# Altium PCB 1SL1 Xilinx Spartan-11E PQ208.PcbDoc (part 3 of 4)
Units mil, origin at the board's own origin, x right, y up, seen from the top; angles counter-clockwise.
Board outline 7086.61 x 1988.19 mil, 2 copper layers (Top Layer, Bottom Layer), stack 29.698 mil thick; 115 components, 126 nets, 642 pads, 225 vias.
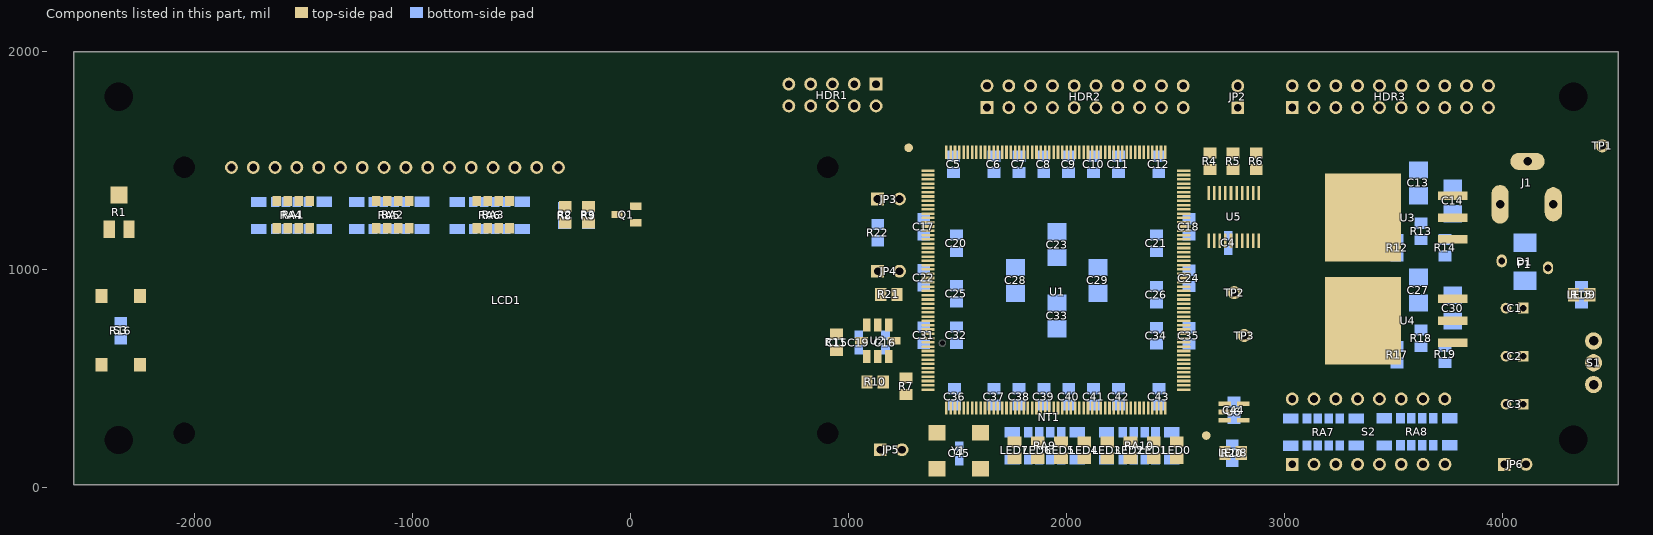
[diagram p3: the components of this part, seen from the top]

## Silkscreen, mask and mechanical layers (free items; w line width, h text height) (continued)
19_FABRICATION_NOTES:
  text "N" at 5217.99,384.2 h46.78
  text "O" at 5243.96,384.2 h46.78
  text "T" at 5269.93,384.2 h46.78
  text "E" at 5288.48,384.2 h46.78
  text "S" at 5307.03,384.2 h46.78
  text "U" at 5333,384.2 h46.78
  text "N" at 5358.97,384.2 h46.78
  text "L" at 5384.93,384.2 h46.78
  text "E" at 5403.48,384.2 h46.78
  text "S" at 5422.03,384.2 h46.78
  text "S" at 5440.58,384.2 h46.78
  text "O" at 5466.55,384.2 h46.78
  text "T" at 5492.52,384.2 h46.78
  text "H" at 5511.07,384.2 h46.78
  text "E" at 5537.04,384.2 h46.78
  text "R" at 5555.58,384.2 h46.78
  text "W" at 5577.84,384.2 h46.78
  text "I" at 5614.94,384.2 h46.78
  text "S" at 5626.07,384.2 h46.78
  text "E" at 5644.62,384.2 h46.78
  text "S" at 5670.59,384.2 h46.78
  text "P" at 5689.14,384.2 h46.78
  text "E" at 5711.4,384.2 h46.78
  text "C" at 5729.94,384.2 h46.78
  text "I" at 5752.2,384.2 h46.78
  text "F" at 5763.33,384.2 h46.78
  text "I" at 5781.88,384.2 h46.78
  text "E" at 5793.01,384.2 h46.78
  text "D" at 5811.56,384.2 h46.78
  text ":" at 5837.53,384.2 h46.78
  text "1" at 5251.37,321.13 h46.78
  text "A" at 5325.54,298.87 h46.78
  text "L" at 5347.8,298.87 h46.78
  text "L" at 5366.35,298.87 h46.78
  text "H" at 5392.32,298.87 h46.78
  text "O" at 5418.29,298.87 h46.78
  text "L" at 5444.26,298.87 h46.78
  text "E" at 5462.81,298.87 h46.78
  text "S" at 5481.35,298.87 h46.78
  text "F" at 5507.32,298.87 h46.78
  text "I" at 5525.87,298.87 h46.78
  text "N" at 5537,298.87 h46.78
  text "I" at 5562.97,298.87 h46.78
  text "S" at 5574.1,298.87 h46.78
  text "H" at 5592.65,298.87 h46.78
  text "E" at 5618.62,298.87 h46.78
  text "D" at 5637.17,298.87 h46.78
  text "S" at 5670.55,298.87 h46.78
  text "I" at 5689.1,298.87 h46.78
  text "Z" at 5700.23,298.87 h46.78
  text "E" at 5718.78,298.87 h46.78
  text "A" at 5744.75,298.87 h46.78
  text "S" at 5767.01,298.87 h46.78
  text "S" at 5792.98,298.87 h46.78
  text "H" at 5811.53,298.87 h46.78
  text "O" at 5837.5,298.87 h46.78
  text "W" at 5863.46,298.87 h46.78
  text "N" at 5900.56,298.87 h46.78
  text "." at 5926.53,298.87 h46.78
  text "M" at 5325.54,235.81 h46.78
  text "A" at 5358.93,235.81 h46.78
  text "T" at 5381.19,235.81 h46.78
  text "E" at 5399.74,235.81 h46.78
  text "R" at 5418.29,235.81 h46.78
  text "I" at 5440.55,235.81 h46.78
  text "A" at 5451.68,235.81 h46.78
  text "L" at 5473.93,235.81 h46.78
  text ":" at 5492.48,235.81 h46.78
  text "0" at 5511.03,235.81 h46.78
  text "." at 5533.29,235.81 h46.78
  text "0" at 5544.42,235.81 h46.78
  text "6" at 5566.68,235.81 h46.78
  text "2" at 5588.94,235.81 h46.78
  text "I" at 5618.62,235.81 h46.78
  text "N" at 5629.75,235.81 h46.78
  text "F" at 5663.13,235.81 h46.78
  text "I" at 5681.68,235.81 h46.78
  text "B" at 5692.81,235.81 h46.78
  text "E" at 5715.07,235.81 h46.78
  text "R" at 5733.62,235.81 h46.78
  text "G" at 5755.88,235.81 h46.78
  text "L" at 5781.85,235.81 h46.78
  text "A" at 5800.4,235.81 h46.78
  text "S" at 5822.66,235.81 h46.78
  text "S" at 5841.21,235.81 h46.78
  text "R" at 5867.17,235.81 h46.78
  text "E" at 5889.43,235.81 h46.78
  text "I" at 5907.98,235.81 h46.78
  text "N" at 5919.11,235.81 h46.78
  text "F" at 5945.08,235.81 h46.78
  text "O" at 5963.63,235.81 h46.78
  text "R" at 5989.6,235.81 h46.78
  text "C" at 6011.86,235.81 h46.78
  text "E" at 6034.11,235.81 h46.78
  text "D" at 6052.66,235.81 h46.78
  text "E" at 6086.05,235.81 h46.78
  text "P" at 6104.6,235.81 h46.78
  text "O" at 6126.86,235.81 h46.78
  text "X" at 6152.83,235.81 h46.78
  text "Y" at 6175.09,235.81 h46.78
  text "," at 6193.64,235.81 h46.78
  text "2" at 5251.37,228.39 h46.78
  text "N" at 5325.54,180.16 h46.78
  text "E" at 5351.51,180.16 h46.78
  text "M" at 5370.06,180.16 h46.78
  text "A" at 5403.45,180.16 h46.78
  text "G" at 5433.13,180.16 h46.78
  text "R" at 5459.1,180.16 h46.78
  text "A" at 5481.35,180.16 h46.78
  text "D" at 5503.61,180.16 h46.78
  text "E" at 5529.58,180.16 h46.78
  text "F" at 5555.55,180.16 h46.78
  text "R" at 5574.1,180.16 h46.78
  text "-" at 5596.36,180.16 h46.78
  text "4" at 5607.49,180.16 h46.78
  text "," at 5629.75,180.16 h46.78
  text "N" at 5648.3,180.16 h46.78
  text "A" at 5674.26,180.16 h46.78
  text "T" at 5696.52,180.16 h46.78
  text "U" at 5715.07,180.16 h46.78
  text "R" at 5741.04,180.16 h46.78
  text "A" at 5763.3,180.16 h46.78
  text "L" at 5785.56,180.16 h46.78
  text "C" at 5811.53,180.16 h46.78
  text "O" at 5833.79,180.16 h46.78
  text "L" at 5859.75,180.16 h46.78
  text "O" at 5878.3,180.16 h46.78
  text "R" at 5904.27,180.16 h46.78
  text "W" at 5933.95,180.16 h46.78
  text "I" at 5971.05,180.16 h46.78
  text "T" at 5982.18,180.16 h46.78
  text "H" at 6000.73,180.16 h46.78
  text "O" at 6026.7,180.16 h46.78
  text "U" at 6052.66,180.16 h46.78
  text "T" at 6078.63,180.16 h46.78
  text "O" at 5325.54,124.51 h46.78
  text "P" at 5351.51,124.51 h46.78
  text "A" at 5373.77,124.51 h46.78
  text "Q" at 5396.03,124.51 h46.78
  text "U" at 5422,124.51 h46.78
  text "E" at 5447.97,124.51 h46.78
  text "R" at 5466.52,124.51 h46.78
  text ";" at 5488.77,124.51 h46.78
  text "1" at 5507.32,124.51 h46.78
  text "O" at 5537,124.51 h46.78
  text "Z" at 5562.97,124.51 h46.78
  text "C" at 5588.94,124.51 h46.78
  text "O" at 5611.2,124.51 h46.78
  text "P" at 5637.17,124.51 h46.78
  text "P" at 5659.43,124.51 h46.78
  text "E" at 5681.68,124.51 h46.78
  text "R" at 5700.23,124.51 h46.78
  text "C" at 5729.91,124.51 h46.78
  text "L" at 5752.17,124.51 h46.78
  text "A" at 5770.72,124.51 h46.78
  text "D" at 5792.98,124.51 h46.78
  text "O" at 5826.37,124.51 h46.78
  text "U" at 5852.33,124.51 h46.78
  text "T" at 5878.3,124.51 h46.78
  text "E" at 5896.85,124.51 h46.78
  text "R" at 5915.4,124.51 h46.78
  text "L" at 5945.08,124.51 h46.78
  text "A" at 5963.63,124.51 h46.78
  text "Y" at 5985.89,124.51 h46.78
  text "E" at 6004.44,124.51 h46.78
  text "R" at 6022.99,124.51 h46.78
  text "S" at 6045.24,124.51 h46.78
  text "." at 6063.79,124.51 h46.78
  text "T" at 6082.34,124.51 h46.78
  text "H" at 6100.89,124.51 h46.78
  text "E" at 6126.86,124.51 h46.78
  text "P" at 5325.54,68.87 h46.78
  text "R" at 5347.8,68.87 h46.78
  text "I" at 5370.06,68.87 h46.78
  text "N" at 5381.19,68.87 h46.78
  text "T" at 5407.16,68.87 h46.78
  text "E" at 5425.71,68.87 h46.78
  text "D" at 5444.26,68.87 h46.78
  text "W" at 5477.64,68.87 h46.78
  text "I" at 5514.74,68.87 h46.78
  text "R" at 5525.87,68.87 h46.78
  text "I" at 5548.13,68.87 h46.78
  text "N" at 5559.26,68.87 h46.78
  text "G" at 5585.23,68.87 h46.78
  text "B" at 5618.62,68.87 h46.78
  text "O" at 5640.88,68.87 h46.78
  text "A" at 5666.84,68.87 h46.78
  text "R" at 5689.1,68.87 h46.78
  text "D" at 5711.36,68.87 h46.78
  text "M" at 5744.75,68.87 h46.78
  text "A" at 5778.14,68.87 h46.78
  text "T" at 5800.4,68.87 h46.78
  text "E" at 5818.95,68.87 h46.78
  text "R" at 5837.5,68.87 h46.78
  text "I" at 5859.75,68.87 h46.78
  text "A" at 5870.88,68.87 h46.78
  text "L" at 5893.14,68.87 h46.78
  text "M" at 5919.11,68.87 h46.78
  text "U" at 5952.5,68.87 h46.78
  text "S" at 5978.47,68.87 h46.78
  text "T" at 5997.02,68.87 h46.78
  text "H" at 6022.99,68.87 h46.78
  text "A" at 6048.95,68.87 h46.78
  text "V" at 6071.21,68.87 h46.78
  text "E" at 6093.47,68.87 h46.78
  text "A" at 6119.44,68.87 h46.78
  text "C" at 5325.54,13.22 h46.78
  text "P" at 5347.8,13.22 h46.78
  text "M" at 5370.06,13.22 h46.78
  text "P" at 5403.45,13.22 h46.78
  text "A" at 5425.71,13.22 h46.78
  text "R" at 5447.97,13.22 h46.78
  text "A" at 5470.23,13.22 h46.78
  text "T" at 5492.48,13.22 h46.78
  text "I" at 5511.03,13.22 h46.78
  text "V" at 5522.16,13.22 h46.78
  text "E" at 5544.42,13.22 h46.78
  text "T" at 5570.39,13.22 h46.78
  text "R" at 5588.94,13.22 h46.78
  text "A" at 5611.2,13.22 h46.78
  text "C" at 5633.46,13.22 h46.78
  text "K" at 5655.72,13.22 h46.78
  text "I" at 5677.97,13.22 h46.78
  text "N" at 5689.1,13.22 h46.78
  text "G" at 5715.07,13.22 h46.78
  text "I" at 5748.46,13.22 h46.78
  text "N" at 5759.59,13.22 h46.78
  text "D" at 5785.56,13.22 h46.78
  text "E" at 5811.53,13.22 h46.78
  text "X" at 5830.08,13.22 h46.78
  text "(" at 5859.75,13.22 h46.78
  text "C" at 5870.88,13.22 h46.78
  text "T" at 5893.14,13.22 h46.78
  text "I" at 5911.69,13.22 h46.78
  text ")" at 5922.82,13.22 h46.78
  text "O" at 5941.37,13.22 h46.78
  text "F" at 5967.34,13.22 h46.78
  text "A" at 5993.31,13.22 h46.78
  text "T" at 6015.57,13.22 h46.78
  text "L" at 6041.53,13.22 h46.78
  text "E" at 6060.08,13.22 h46.78
  text "A" at 6078.63,13.22 h46.78
  text "S" at 6100.89,13.22 h46.78
  text "T" at 6119.44,13.22 h46.78
  text "1" at 6145.41,13.22 h46.78
  text "7" at 6167.67,13.22 h46.78
  text "5" at 6189.93,13.22 h46.78
  text "A" at 5325.54,-42.43 h46.78
  text "N" at 5347.8,-42.43 h46.78
  text "D" at 5373.77,-42.43 h46.78
  text "A" at 5407.16,-42.43 h46.78
  text "U" at 5436.84,-42.43 h46.78
  text "L" at 5462.81,-42.43 h46.78
  text "9" at 5488.77,-42.43 h46.78
  text "4" at 5511.03,-42.43 h46.78
  text "V" at 5533.29,-42.43 h46.78
  text "0" at 5555.55,-42.43 h46.78
  text "F" at 5585.23,-42.43 h46.78
  text "L" at 5603.78,-42.43 h46.78
  text "A" at 5622.33,-42.43 h46.78
  text "M" at 5644.59,-42.43 h46.78
  text "M" at 5677.97,-42.43 h46.78
  text "A" at 5711.36,-42.43 h46.78
  text "B" at 5733.62,-42.43 h46.78
  text "I" at 5755.88,-42.43 h46.78
  text "L" at 5767.01,-42.43 h46.78
  text "I" at 5785.56,-42.43 h46.78
  text "T" at 5796.69,-42.43 h46.78
  text "Y" at 5815.24,-42.43 h46.78
  text "R" at 5841.21,-42.43 h46.78
  text "A" at 5863.46,-42.43 h46.78
  text "T" at 5885.72,-42.43 h46.78
  text "I" at 5904.27,-42.43 h46.78
  text "N" at 5915.4,-42.43 h46.78
  text "G" at 5941.37,-42.43 h46.78
  text "." at 5967.34,-42.43 h46.78
  text "3" at 5251.37,-112.91 h46.78
  text "F" at 5325.54,-135.17 h46.78
  text "I" at 5344.09,-135.17 h46.78
  text "N" at 5355.22,-135.17 h46.78
  text "I" at 5381.19,-135.17 h46.78
  text "S" at 5392.32,-135.17 h46.78
  text "H" at 5410.87,-135.17 h46.78
  text ":" at 5436.84,-135.17 h46.78
  text "E" at 5455.39,-135.17 h46.78
  text "N" at 5473.93,-135.17 h46.78
  text "I" at 5499.9,-135.17 h46.78
  text "G" at 5511.03,-135.17 h46.78
  text "P" at 5544.42,-135.17 h46.78
  text "E" at 5566.68,-135.17 h46.78
  text "R" at 5585.23,-135.17 h46.78
  text "I" at 5614.91,-135.17 h46.78
  text "P" at 5626.04,-135.17 h46.78
  text "C" at 5648.3,-135.17 h46.78
  text "-" at 5670.55,-135.17 h46.78
  text "4" at 5681.68,-135.17 h46.78
  text "5" at 5703.94,-135.17 h46.78
  text "5" at 5726.2,-135.17 h46.78
  text "2" at 5748.46,-135.17 h46.78
  text "." at 5770.72,-135.17 h46.78
  text "A" at 5325.54,-198.24 h46.78
  text "P" at 5347.8,-198.24 h46.78
  text "P" at 5370.06,-198.24 h46.78
  text "L" at 5392.32,-198.24 h46.78
  text "Y" at 5410.87,-198.24 h46.78
  text "G" at 5436.84,-198.24 h46.78
  text "R" at 5462.81,-198.24 h46.78
  text "E" at 5485.06,-198.24 h46.78
  text "E" at 5503.61,-198.24 h46.78
  text "N" at 5522.16,-198.24 h46.78
  text "S" at 5555.55,-198.24 h46.78
  text "O" at 5574.1,-198.24 h46.78
  text "L" at 5600.07,-198.24 h46.78
  text "D" at 5618.62,-198.24 h46.78
  text "E" at 5644.59,-198.24 h46.78
  text "R" at 5663.13,-198.24 h46.78
  text "M" at 5692.81,-198.24 h46.78
  text "A" at 5726.2,-198.24 h46.78
  text "S" at 5748.46,-198.24 h46.78
  text "K" at 5767.01,-198.24 h46.78
  text "O" at 5796.69,-198.24 h46.78
  text "V" at 5822.66,-198.24 h46.78
  text "E" at 5844.92,-198.24 h46.78
  text "R" at 5863.46,-198.24 h46.78
  text "B" at 5893.14,-198.24 h46.78
  text "A" at 5915.4,-198.24 h46.78
  text "R" at 5937.66,-198.24 h46.78
  text "E" at 5959.92,-198.24 h46.78
  text "C" at 5985.89,-198.24 h46.78
  text "O" at 6008.15,-198.24 h46.78
  text "P" at 6034.11,-198.24 h46.78
  text "P" at 6056.37,-198.24 h46.78
  text "E" at 6078.63,-198.24 h46.78
  text "R" at 6097.18,-198.24 h46.78
  text "(" at 6126.86,-198.24 h46.78
  text "B" at 6137.99,-198.24 h46.78
  text "O" at 6160.25,-198.24 h46.78
  text "T" at 6186.22,-198.24 h46.78
  text "H" at 6204.77,-198.24 h46.78
  text "4" at 5251.37,-205.66 h46.78
  text "S" at 5325.54,-253.89 h46.78
  text "I" at 5344.09,-253.89 h46.78
  text "D" at 5355.22,-253.89 h46.78
  text "E" at 5381.19,-253.89 h46.78
  text "S" at 5399.74,-253.89 h46.78
  text ")" at 5418.29,-253.89 h46.78
  text "." at 5429.42,-253.89 h46.78
  text "T" at 5325.54,-316.95 h46.78
  text "O" at 5344.09,-316.95 h46.78
  text "B" at 5377.48,-316.95 h46.78
  text "E" at 5399.74,-316.95 h46.78
  text "S" at 5425.71,-316.95 h46.78
  text "I" at 5444.26,-316.95 h46.78
  text "L" at 5455.39,-316.95 h46.78
  text "K" at 5473.93,-316.95 h46.78
  text "S" at 5496.19,-316.95 h46.78
  text "C" at 5514.74,-316.95 h46.78
  text "R" at 5537,-316.95 h46.78
  text "E" at 5559.26,-316.95 h46.78
  text "E" at 5577.81,-316.95 h46.78
  text "N" at 5596.36,-316.95 h46.78
  text "E" at 5622.33,-316.95 h46.78
  text "D" at 5640.88,-316.95 h46.78
  text "W" at 5674.26,-316.95 h46.78
  text "H" at 5711.36,-316.95 h46.78
  text "I" at 5737.33,-316.95 h46.78
  text "T" at 5748.46,-316.95 h46.78
  text "E" at 5767.01,-316.95 h46.78
  text "O" at 5792.98,-316.95 h46.78
  text "N" at 5818.95,-316.95 h46.78
  text "(" at 5852.33,-316.95 h46.78
  text "B" at 5863.46,-316.95 h46.78
  text "O" at 5885.72,-316.95 h46.78
  text "T" at 5911.69,-316.95 h46.78
  text "H" at 5930.24,-316.95 h46.78
  text "S" at 5963.63,-316.95 h46.78
  text "I" at 5982.18,-316.95 h46.78
  text "D" at 5993.31,-316.95 h46.78
  text "E" at 6019.28,-316.95 h46.78
  text "S" at 6037.82,-316.95 h46.78
  text ")" at 6056.37,-316.95 h46.78
  text "P" at 6074.92,-316.95 h46.78
  text "E" at 6097.18,-316.95 h46.78
  text "R" at 6115.73,-316.95 h46.78
  text "5" at 5251.37,-324.37 h46.78
  text "\"" at 5325.54,-372.6 h46.78
  text "S" at 5340.38,-372.6 h46.78
  text "I" at 5358.93,-372.6 h46.78
  text "L" at 5370.06,-372.6 h46.78
  text "K" at 5388.61,-372.6 h46.78
  text "S" at 5410.87,-372.6 h46.78
  text "C" at 5429.42,-372.6 h46.78
  text "R" at 5451.68,-372.6 h46.78
  text "E" at 5473.93,-372.6 h46.78
  text "E" at 5492.48,-372.6 h46.78
  text "N" at 5511.03,-372.6 h46.78
  text "\"" at 5537,-372.6 h46.78
  text "A" at 5559.26,-372.6 h46.78
  text "R" at 5581.52,-372.6 h46.78
  text "T" at 5603.78,-372.6 h46.78
  text "W" at 5622.33,-372.6 h46.78
  text "O" at 5659.43,-372.6 h46.78
  text "R" at 5685.39,-372.6 h46.78
  text "K" at 5707.65,-372.6 h46.78
  text "." at 5729.91,-372.6 h46.78
  text "6" at 5251.37,-443.09 h46.78
  text "P" at 5325.54,-443.09 h46.78
  text "R" at 5347.8,-443.09 h46.78
  text "I" at 5370.06,-443.09 h46.78
  text "N" at 5381.19,-443.09 h46.78
  text "T" at 5407.16,-443.09 h46.78
  text "E" at 5425.71,-443.09 h46.78
  text "D" at 5444.26,-443.09 h46.78
  text "W" at 5477.64,-443.09 h46.78
  text "I" at 5514.74,-443.09 h46.78
  text "R" at 5525.87,-443.09 h46.78
  text "I" at 5548.13,-443.09 h46.78
  text "N" at 5559.26,-443.09 h46.78
  text "G" at 5585.23,-443.09 h46.78
  text "B" at 5618.62,-443.09 h46.78
  text "O" at 5640.88,-443.09 h46.78
  text "A" at 5666.84,-443.09 h46.78
  text "R" at 5689.1,-443.09 h46.78
  text "D" at 5711.36,-443.09 h46.78
  text "T" at 5744.75,-443.09 h46.78
  text "O" at 5763.3,-443.09 h46.78
  text "B" at 5796.69,-443.09 h46.78
  text "E" at 5818.95,-443.09 h46.78
  text "E" at 5844.92,-443.09 h46.78
  text "L" at 5863.46,-443.09 h46.78
  text "E" at 5882.01,-443.09 h46.78
  text "C" at 5900.56,-443.09 h46.78
  text "T" at 5922.82,-443.09 h46.78
  text "R" at 5941.37,-443.09 h46.78
  text "I" at 5963.63,-443.09 h46.78
  text "C" at 5974.76,-443.09 h46.78
  text "A" at 5997.02,-443.09 h46.78
  text "L" at 6019.28,-443.09 h46.78
  text "L" at 6037.82,-443.09 h46.78
  text "Y" at 6056.37,-443.09 h46.78
  text "T" at 6082.34,-443.09 h46.78
  text "E" at 6100.89,-443.09 h46.78
  text "S" at 6119.44,-443.09 h46.78
  text "T" at 6137.99,-443.09 h46.78
  text "E" at 6156.54,-443.09 h46.78
  text "D" at 6175.09,-443.09 h46.78
  text "B" at 5325.54,-498.73 h46.78
  text "Y" at 5347.8,-498.73 h46.78
  text "F" at 5373.77,-498.73 h46.78
  text "A" at 5392.32,-498.73 h46.78
  text "B" at 5414.58,-498.73 h46.78
  text "R" at 5436.84,-498.73 h46.78
  text "I" at 5459.1,-498.73 h46.78
  text "C" at 5470.23,-498.73 h46.78
  text "A" at 5492.48,-498.73 h46.78
  text "T" at 5514.74,-498.73 h46.78
  text "O" at 5533.29,-498.73 h46.78
  text "R" at 5559.26,-498.73 h46.78
  text "F" at 5588.94,-498.73 h46.78
  text "O" at 5607.49,-498.73 h46.78
  text "R" at 5633.46,-498.73 h46.78
  text "T" at 5663.13,-498.73 h46.78
  text "R" at 5681.68,-498.73 h46.78
  text "A" at 5703.94,-498.73 h46.78
  text "C" at 5726.2,-498.73 h46.78
  text "E" at 5748.46,-498.73 h46.78
  text "C" at 5774.43,-498.73 h46.78
  text "O" at 5796.69,-498.73 h46.78
  text "N" at 5822.66,-498.73 h46.78
  text "T" at 5848.62,-498.73 h46.78
  text "I" at 5867.17,-498.73 h46.78
  text "N" at 5878.3,-498.73 h46.78
  text "U" at 5904.27,-498.73 h46.78
  text "I" at 5930.24,-498.73 h46.78
  text "T" at 5941.37,-498.73 h46.78
  text "Y" at 5959.92,-498.73 h46.78
  text "A" at 5985.89,-498.73 h46.78
  text "N" at 6008.15,-498.73 h46.78
  text "D" at 6034.11,-498.73 h46.78
  text "P" at 6067.5,-498.73 h46.78
  text "R" at 6089.76,-498.73 h46.78
  text "O" at 6112.02,-498.73 h46.78
  text "O" at 6137.99,-498.73 h46.78
  text "F" at 6163.96,-498.73 h46.78
  text "A" at 5325.54,-554.38 h46.78
  text "G" at 5347.8,-554.38 h46.78
  text "A" at 5373.77,-554.38 h46.78
  text "I" at 5396.03,-554.38 h46.78
  text "N" at 5407.16,-554.38 h46.78
  text "S" at 5433.13,-554.38 h46.78
  text "T" at 5451.68,-554.38 h46.78
  text "T" at 5477.64,-554.38 h46.78
  text "R" at 5496.19,-554.38 h46.78
  text "A" at 5518.45,-554.38 h46.78
  text "C" at 5540.71,-554.38 h46.78
  text "E" at 5562.97,-554.38 h46.78
  text "S" at 5588.94,-554.38 h46.78
  text "H" at 5607.49,-554.38 h46.78
  text "O" at 5633.46,-554.38 h46.78
  text "R" at 5659.43,-554.38 h46.78
  text "T" at 5681.68,-554.38 h46.78
  text "S" at 5700.23,-554.38 h46.78
  text "." at 5718.78,-554.38 h46.78
  text "7" at 5251.37,-610.03 h46.78
  text "A" at 5325.54,-632.29 h46.78
  text "L" at 5347.8,-632.29 h46.78
  text "L" at 5366.35,-632.29 h46.78
  text "R" at 5392.32,-632.29 h46.78
  text "A" at 5414.58,-632.29 h46.78
  text "D" at 5436.84,-632.29 h46.78
  text "I" at 5462.81,-632.29 h46.78
  text "U" at 5473.93,-632.29 h46.78
  text "S" at 5499.9,-632.29 h46.78
  text "0" at 5525.87,-632.29 h46.78
  text "." at 5548.13,-632.29 h46.78
  text "0" at 5559.26,-632.29 h46.78
  text "4" at 5581.52,-632.29 h46.78
  text "7" at 5603.78,-632.29 h46.78
  text "U" at 5633.46,-632.29 h46.78
  text "N" at 5659.43,-632.29 h46.78
  text "L" at 5685.39,-632.29 h46.78
  text "E" at 5703.94,-632.29 h46.78
  text "S" at 5722.49,-632.29 h46.78
  text "S" at 5741.04,-632.29 h46.78
  text "O" at 5767.01,-632.29 h46.78
  text "T" at 5792.98,-632.29 h46.78
  text "H" at 5811.53,-632.29 h46.78
  text "E" at 5837.5,-632.29 h46.78
  text "R" at 5856.04,-632.29 h46.78
  text "W" at 5878.3,-632.29 h46.78
  text "I" at 5915.4,-632.29 h46.78
  text "S" at 5926.53,-632.29 h46.78
  text "E" at 5945.08,-632.29 h46.78
  text "N" at 5971.05,-632.29 h46.78
  text "O" at 5997.02,-632.29 h46.78
  text "T" at 6022.99,-632.29 h46.78
  text "E" at 6041.53,-632.29 h46.78
  text "D" at 6060.08,-632.29 h46.78
  text "." at 6086.05,-632.29 h46.78
  text "F" at 5325.54,-695.35 h46.78
  text "A" at 5344.09,-695.35 h46.78
  text "B" at 5366.35,-695.35 h46.78
  text "R" at 5388.61,-695.35 h46.78
  text "I" at 5410.87,-695.35 h46.78
  text "C" at 5422,-695.35 h46.78
  text "A" at 5444.26,-695.35 h46.78
  text "T" at 5466.52,-695.35 h46.78
  text "O" at 5485.06,-695.35 h46.78
  text "R" at 5511.03,-695.35 h46.78
  text "S" at 5540.71,-695.35 h46.78
  text "H" at 5559.26,-695.35 h46.78
  text "A" at 5585.23,-695.35 h46.78
  text "L" at 5607.49,-695.35 h46.78
  text "L" at 5626.04,-695.35 h46.78
  text "A" at 5652.01,-695.35 h46.78
  text "P" at 5674.26,-695.35 h46.78
  text "P" at 5696.52,-695.35 h46.78
  text "L" at 5718.78,-695.35 h46.78
  text "Y" at 5737.33,-695.35 h46.78
  text "D" at 5763.3,-695.35 h46.78
  text "A" at 5789.27,-695.35 h46.78
  text "T" at 5811.53,-695.35 h46.78
  text "E" at 5830.08,-695.35 h46.78
  text "C" at 5856.04,-695.35 h46.78
  text "O" at 5878.3,-695.35 h46.78
  text "D" at 5904.27,-695.35 h46.78
  text "E" at 5930.24,-695.35 h46.78
  text "," at 5948.79,-695.35 h46.78
  text "F" at 5967.34,-695.35 h46.78
  text "A" at 5985.89,-695.35 h46.78
  text "B" at 6008.15,-695.35 h46.78
  text "R" at 6030.41,-695.35 h46.78
  text "I" at 6052.66,-695.35 h46.78
  text "C" at 6063.79,-695.35 h46.78
  text "A" at 6086.05,-695.35 h46.78
  text "T" at 6108.31,-695.35 h46.78
  text "O" at 6126.86,-695.35 h46.78
  text "R" at 6152.83,-695.35 h46.78
  text "'" at 6175.09,-695.35 h46.78
  text "S" at 6182.51,-695.35 h46.78
  text "8" at 5251.37,-702.77 h46.78
  text "C" at 5325.54,-751 h46.78
  text "A" at 5347.8,-751 h46.78
  text "N" at 5370.06,-751 h46.78
  text "G" at 5396.03,-751 h46.78
  text "C" at 5429.42,-751 h46.78
  text "O" at 5451.68,-751 h46.78
  text "D" at 5477.64,-751 h46.78
  text "E" at 5503.61,-751 h46.78
  text "A" at 5529.58,-751 h46.78
  text "N" at 5551.84,-751 h46.78
  text "D" at 5577.81,-751 h46.78
  text "U" at 5611.2,-751 h46.78
  text "L" at 5637.17,-751 h46.78
  text "M" at 5663.13,-751 h46.78
  text "A" at 5696.52,-751 h46.78
  text "R" at 5718.78,-751 h46.78
  text "K" at 5741.04,-751 h46.78
  text "I" at 5763.3,-751 h46.78
  text "N" at 5774.43,-751 h46.78
  text "G" at 5800.4,-751 h46.78
  text "T" at 5833.79,-751 h46.78
  text "O" at 5852.33,-751 h46.78
  text "S" at 5885.72,-751 h46.78
  text "E" at 5904.27,-751 h46.78
  text "C" at 5922.82,-751 h46.78
  text "O" at 5945.08,-751 h46.78
  text "N" at 5971.05,-751 h46.78
  text "D" at 5997.02,-751 h46.78
  text "A" at 6022.99,-751 h46.78
  text "R" at 6045.24,-751 h46.78
  text "Y" at 6067.5,-751 h46.78
  text "S" at 6093.47,-751 h46.78
  text "I" at 6112.02,-751 h46.78
  text "D" at 6123.15,-751 h46.78
  text "E" at 6149.12,-751 h46.78
  text "W" at 5325.54,-806.65 h46.78
  text "H" at 5362.64,-806.65 h46.78
  text "E" at 5388.61,-806.65 h46.78
  text "R" at 5407.16,-806.65 h46.78
  text "E" at 5429.42,-806.65 h46.78
  text "I" at 5455.39,-806.65 h46.78
  text "N" at 5466.52,-806.65 h46.78
  text "D" at 5492.48,-806.65 h46.78
  text "I" at 5518.45,-806.65 h46.78
  text "C" at 5529.58,-806.65 h46.78
  text "A" at 5551.84,-806.65 h46.78
  text "T" at 5574.1,-806.65 h46.78
  text "E" at 5592.65,-806.65 h46.78
  text "D" at 5611.2,-806.65 h46.78
  text "." at 5637.17,-806.65 h46.78
  text "M" at 5655.72,-806.65 h46.78
  text "A" at 5689.1,-806.65 h46.78
  text "R" at 5711.36,-806.65 h46.78
  text "K" at 5733.62,-806.65 h46.78
  text "I" at 5755.88,-806.65 h46.78
  text "N" at 5767.01,-806.65 h46.78
  text "G" at 5792.98,-806.65 h46.78
  text "T" at 5826.37,-806.65 h46.78
  text "O" at 5844.92,-806.65 h46.78
  text "B" at 5878.3,-806.65 h46.78
  text "E" at 5900.56,-806.65 h46.78
  text "C" at 5926.53,-806.65 h46.78
  text "O" at 5948.79,-806.65 h46.78
  text "P" at 5974.76,-806.65 h46.78
  text "P" at 5997.02,-806.65 h46.78
  text "E" at 6019.28,-806.65 h46.78
  text "R" at 6037.82,-806.65 h46.78
  text "E" at 6067.5,-806.65 h46.78
  text "T" at 6086.05,-806.65 h46.78
  text "C" at 6104.6,-806.65 h46.78
  text "H" at 6126.86,-806.65 h46.78
  text "E" at 6152.83,-806.65 h46.78
  text "D" at 6171.38,-806.65 h46.78
  text "." at 6197.35,-806.65 h46.78
  text "F" at 5325.54,-869.71 h46.78
  text "A" at 5344.09,-869.71 h46.78
  text "B" at 5366.35,-869.71 h46.78
  text "R" at 5388.61,-869.71 h46.78
  text "I" at 5410.87,-869.71 h46.78
  text "C" at 5422,-869.71 h46.78
  text "A" at 5444.26,-869.71 h46.78
  text "T" at 5466.52,-869.71 h46.78
  text "O" at 5485.06,-869.71 h46.78
  text "R" at 5511.03,-869.71 h46.78
  text "S" at 5540.71,-869.71 h46.78
  text "H" at 5559.26,-869.71 h46.78
  text "A" at 5585.23,-869.71 h46.78
  text "L" at 5607.49,-869.71 h46.78
  text "L" at 5626.04,-869.71 h46.78
  text "A" at 5652.01,-869.71 h46.78
  text "P" at 5674.26,-869.71 h46.78
  text "P" at 5696.52,-869.71 h46.78
  text "L" at 5718.78,-869.71 h46.78
  text "Y" at 5737.33,-869.71 h46.78
  text "C" at 5763.3,-869.71 h46.78
  text "O" at 5785.56,-869.71 h46.78
  text "U" at 5811.53,-869.71 h46.78
  text "N" at 5837.5,-869.71 h46.78
  text "T" at 5863.46,-869.71 h46.78
  text "R" at 5882.01,-869.71 h46.78
  text "Y" at 5904.27,-869.71 h46.78
  text "O" at 5930.24,-869.71 h46.78
  text "F" at 5956.21,-869.71 h46.78
  text "O" at 5982.18,-869.71 h46.78
  text "R" at 6008.15,-869.71 h46.78
  text "I" at 6030.41,-869.71 h46.78
  text "G" at 6041.53,-869.71 h46.78
  text "I" at 6067.5,-869.71 h46.78
  text "N" at 6078.63,-869.71 h46.78
  text "9" at 5251.37,-877.13 h46.78
  text "M" at 5325.54,-925.36 h46.78
  text "A" at 5358.93,-925.36 h46.78
  text "R" at 5381.19,-925.36 h46.78
  text "K" at 5403.45,-925.36 h46.78
  text "I" at 5425.71,-925.36 h46.78
  text "N" at 5436.84,-925.36 h46.78
  text "G" at 5462.81,-925.36 h46.78
  text "T" at 5496.19,-925.36 h46.78
  text "O" at 5514.74,-925.36 h46.78
  text "P" at 5548.13,-925.36 h46.78
  text "R" at 5570.39,-925.36 h46.78
  text "I" at 5592.65,-925.36 h46.78
  text "M" at 5603.78,-925.36 h46.78
  text "A" at 5637.17,-925.36 h46.78
  text "R" at 5659.43,-925.36 h46.78
  text "Y" at 5681.68,-925.36 h46.78
  text "A" at 5707.65,-925.36 h46.78
  text "N" at 5729.91,-925.36 h46.78
  text "D" at 5755.88,-925.36 h46.78
  text "S" at 5789.27,-925.36 h46.78
  text "E" at 5807.82,-925.36 h46.78
  text "C" at 5826.37,-925.36 h46.78
  text "O" at 5848.62,-925.36 h46.78
  text "N" at 5874.59,-925.36 h46.78
  text "D" at 5900.56,-925.36 h46.78
  text "A" at 5926.53,-925.36 h46.78
  text "R" at 5948.79,-925.36 h46.78
  text "Y" at 5971.05,-925.36 h46.78
  text "S" at 5997.02,-925.36 h46.78
  text "I" at 6015.57,-925.36 h46.78
  text "D" at 6026.7,-925.36 h46.78
  text "E" at 6052.66,-925.36 h46.78
  text "W" at 6078.63,-925.36 h46.78
  text "H" at 6115.73,-925.36 h46.78
  text "E" at 6141.7,-925.36 h46.78
  text "R" at 6160.25,-925.36 h46.78
  text "E" at 6182.51,-925.36 h46.78
  text "I" at 5325.54,-981.01 h46.78
  text "N" at 5336.67,-981.01 h46.78
  text "D" at 5362.64,-981.01 h46.78
  text "I" at 5388.61,-981.01 h46.78
  text "C" at 5399.74,-981.01 h46.78
  text "A" at 5422,-981.01 h46.78
  text "T" at 5444.26,-981.01 h46.78
  text "E" at 5462.81,-981.01 h46.78
  text "D" at 5481.35,-981.01 h46.78
  text "." at 5507.32,-981.01 h46.78
  text "M" at 5525.87,-981.01 h46.78
  text "A" at 5559.26,-981.01 h46.78
  text "R" at 5581.52,-981.01 h46.78
  text "K" at 5603.78,-981.01 h46.78
  text "I" at 5626.04,-981.01 h46.78
  text "N" at 5637.17,-981.01 h46.78
  text "G" at 5663.13,-981.01 h46.78
  text "T" at 5696.52,-981.01 h46.78
  text "O" at 5715.07,-981.01 h46.78
  text "B" at 5748.46,-981.01 h46.78
  text "E" at 5770.72,-981.01 h46.78
  text "I" at 5796.69,-981.01 h46.78
  text "N" at 5807.82,-981.01 h46.78
  text "S" at 5841.21,-981.01 h46.78
  text "I" at 5859.75,-981.01 h46.78
  text "L" at 5870.88,-981.01 h46.78
  text "K" at 5889.43,-981.01 h46.78
  text "S" at 5911.69,-981.01 h46.78
  text "C" at 5930.24,-981.01 h46.78
  text "R" at 5952.5,-981.01 h46.78
  text "E" at 5974.76,-981.01 h46.78
  text "E" at 5993.31,-981.01 h46.78
  text "N" at 6011.86,-981.01 h46.78
  text "." at 6037.82,-981.01 h46.78
20_ASSEMBLY_NOTES:
  lines w7.87: 768.56,-246.03 768.56,-320.83 843.36,-246.03 870.13,-246.03 ; 846.51,-320.83 921.31,-246.03 ; 925.25,-320.83 1000.06,-246.03 ; 1003.99,-320.83 1078.8,-246.03 ; 1082.73,-320.83 1157.54,-246.03 ; 1161.47,-320.83 1250.24,-232.44
  lines w8: 768.56,-320.83 1173.28,-320.83 1173.28,-415.32 1303.2,-285.4 1173.28,-155.48 1173.28,-246.03 768.56,-246.03
  text "BOARD TRAVEL" at 655.96,-509.42 h59.06
21_TITLE_BLOCK:
  drawing of 113 lines, arcs and shapes, not listed
  text "DWG. NO." at 6155.1,6215 h30
  text "REV:" at 7165.1,6215 h30
  text "6" at -4018.66,6170 h70
  text "5" at -1523,6170 h70
  text "4" at 966.34,6170 h70
  text "3" at 3473.01,6170 h70
  text "2" at 5972,6170 h70
  text "1" at 8477,6170 h70
  text ".PCB_DWG_NO" at 6370,6125 h50
  text ".PCB_REV" at 7180,6125 h50
  text "T" at -5038,6027.61 h76
  text "H" at -4994.66,6027.61 h76
  text "I" at -4944.64,6027.61 h76
  text "S" at -4924.64,6027.61 h76
  text "D" at -4859.62,6027.61 h76
  text "O" at -4809.61,6027.61 h76
  text "C" at -4754.6,6027.61 h76
  text "U" at -4704.59,6027.61 h76
  text "M" at -4654.57,6027.61 h76
  text "E" at -4596.23,6027.61 h76
  text "N" at -4549.55,6027.61 h76
  text "T" at -4501.2,6027.61 h76
  text "A" at -4437.85,6027.61 h76
  text "N" at -4391.17,6027.61 h76
  text "D" at -4341.16,6027.61 h76
  text "T" at -4272.81,6027.61 h76
  text "H" at -4229.47,6027.61 h76
  text "E" at -4179.46,6027.61 h76
  text "D" at -4114.44,6027.61 h76
  text "A" at -4064.43,6027.61 h76
  text "T" at -4017.75,6027.61 h76
  text "A" at -3976.07,6027.61 h76
  text "D" at -3909.39,6027.61 h76
  text "I" at -3859.38,6027.61 h76
  text "S" at -3841.04,6027.61 h76
  text "C" at -3794.36,6027.61 h76
  text "L" at -3744.35,6027.61 h76
  text "O" at -3706.01,6027.61 h76
  text "S" at -3650.99,6027.61 h76
  text "E" at -3604.31,6027.61 h76
  text "D" at -3557.64,6027.61 h76
  text "H" at -3489.29,6027.61 h76
  text "E" at -3439.27,6027.61 h76
  text "R" at -3392.6,6027.61 h76
  text "E" at -3344.25,6027.61 h76
  text "I" at -3297.57,6027.61 h76
  text "N" at -3277.57,6027.61 h76
  text "O" at -3209.22,6027.61 h76
  text "R" at -3154.2,6027.61 h76
  text "REVISIONS" at 7390,5995 h60
  text "H" at -5038,5947.59 h76
  text "E" at -4987.99,5947.59 h76
  text "R" at -4941.31,5947.59 h76
  text "E" at -4891.3,5947.59 h76
  text "W" at -4846.29,5947.59 h76
  text "I" at -4777.94,5947.59 h76
  text "T" at -4759.6,5947.59 h76
  text "H" at -4716.25,5947.59 h76
  text "I" at -4647.9,5947.59 h76
  text "S" at -4627.9,5947.59 h76
  text "T" at -4562.88,5947.59 h76
  text "H" at -4519.54,5947.59 h76
  text "E" at -4469.53,5947.59 h76
  text "P" at -4404.51,5947.59 h76
  text "R" at -4357.83,5947.59 h76
  text "O" at -4307.82,5947.59 h76
  text "P" at -4253.77,5947.59 h76
  text "E" at -4207.1,5947.59 h76
  text "R" at -4160.42,5947.59 h76
  text "T" at -4112.07,5947.59 h76
  text "Y" at -4068.73,5947.59 h76
  text "O" at -4003.71,5947.59 h76
  text "F" at -3950.37,5947.59 h76
  text "A" at -3887.02,5947.59 h76
  text "L" at -3840.34,5947.59 h76
  text "T" at -3803.66,5947.59 h76
  text "I" at -3760.32,5947.59 h76
  text "U" at -3740.31,5947.59 h76
  text "M" at -3690.3,5947.59 h76
  text "L" at -3613.62,5947.59 h76
  text "I" at -3575.27,5947.59 h76
  text "M" at -3555.27,5947.59 h76
  text "I" at -3498.59,5947.59 h76
  text "T" at -3478.58,5947.59 h76
  text "E" at -3435.24,5947.59 h76
  text "D" at -3388.56,5947.59 h76
  text "A" at -3320.21,5947.59 h76
  text "N" at -3273.53,5947.59 h76
  text "D" at -3223.52,5947.59 h76
  text "M" at -3153.5,5947.59 h76
  text "A" at -3095.15,5947.59 h76
  text "Y" at -3050.14,5947.59 h76
  text "ZONE" at 5805,5870 h60
  text "REV" at 6135,5870 h60
  text "DATE" at 8555,5870 h60
  text "B" at -5038,5867.57 h76
  text "E" at -4991.32,5867.57 h76
  text "F" at -4924.64,5867.57 h76
  text "R" at -4881.3,5867.57 h76
  text "E" at -4831.28,5867.57 h76
  text "E" at -4786.27,5867.57 h76
  text "L" at -4739.59,5867.57 h76
  text "Y" at -4701.25,5867.57 h76
  text "D" at -4634.57,5867.57 h76
  text "I" at -4584.56,5867.57 h76
  text "S" at -4566.22,5867.57 h76
  text "T" at -4519.54,5867.57 h76
  text "R" at -4476.89,5867.57 h76
  text "I" at -4428.54,5867.57 h76
  text "B" at -4408.54,5867.57 h76
  text "U" at -4361.86,5867.57 h76
  text "T" at -4311.85,5867.57 h76
  text "E" at -4268.5,5867.57 h76
  text "D" at -4221.82,5867.57 h76
  text "I" at -4153.47,5867.57 h76
  text "N" at -4133.47,5867.57 h76
  text "W" at -4066.79,5867.57 h76
  text "H" at -3998.44,5867.57 h76
  text "O" at -3950.09,5867.57 h76
  text "L" at -3895.08,5867.57 h76
  text "E" at -3856.73,5867.57 h76
  text "." at -3810.06,5867.57 h76
  text "N" at -3771.71,5867.57 h76
  text "O" at -3721.7,5867.57 h76
  text "R" at -3646.68,5867.57 h76
  text "I" at -3598.34,5867.57 h76
  text "G" at -3578.33,5867.57 h76
  text "H" at -3523.32,5867.57 h76
  text "T" at -3474.97,5867.57 h76
  text "S" at -3431.63,5867.57 h76
  text "A" at -3366.61,5867.57 h76
  text "R" at -3319.94,5867.57 h76
  text "E" at -3269.92,5867.57 h76
  text "DESCRIPTION" at 7150,5865 h60
  text "APPROVED" at 9060,5865 h60
  text "R" at -5038,5787.55 h76
  text "E" at -4987.99,5787.55 h76
  text "S" at -4941.31,5787.55 h76
  text "E" at -4894.63,5787.55 h76
  text "R" at -4847.95,5787.55 h76
  text "V" at -4797.94,5787.55 h76
  text "E" at -4751.26,5787.55 h76
  text "D" at -4704.59,5787.55 h76
  text "O" at -4636.24,5787.55 h76
  text "R" at -4581.22,5787.55 h76
  text "E" at -4511.2,5787.55 h76
  text "X" at -4464.53,5787.55 h76
  text "P" at -4419.52,5787.55 h76
  text "R" at -4372.84,5787.55 h76
  text "E" at -4322.82,5787.55 h76
  text "S" at -4276.15,5787.55 h76
  text "S" at -4229.47,5787.55 h76
  text "O" at -4164.45,5787.55 h76
  text "R" at -4109.44,5787.55 h76
  text "I" at -4041.09,5787.55 h76
  text "M" at -4021.08,5787.55 h76
  text "P" at -3962.74,5787.55 h76
  text "L" at -3916.06,5787.55 h76
  text "I" at -3879.38,5787.55 h76
  text "E" at -3859.38,5787.55 h76
  text "D" at -3812.7,5787.55 h76
  text "W" at -3746.02,5787.55 h76
  text "A" at -3677.67,5787.55 h76
  text "R" at -3630.99,5787.55 h76
  text "A" at -3580.98,5787.55 h76
  text "N" at -3534.3,5787.55 h76
  text "T" at -3485.95,5787.55 h76
  text "E" at -3442.61,5787.55 h76
  text "E" at -3395.93,5787.55 h76
  text "G" at -3334.68,5787.55 h76
  text "I" at -3279.67,5787.55 h76
  text "V" at -3259.66,5787.55 h76
  text "E" at -3212.98,5787.55 h76
  text "N" at -3166.3,5787.55 h76
  text "." at -3117.96,5787.55 h76
  text "A" at 6165,5735 h60
  text "ORIGINAL" at 7225,5735 h60
  text "D" at -5175,5027 h70
  text "D" at 9625,5027 h70
  text "C" at -5175,2647 h70
  text "C" at 9625,2647 h70
  text "B" at -5175,272 h70
  text "B" at 9625,272 h70
  text "DWG. NO." at 9665,-325.1 h30 r270
  text ".PCB_DWG_NO" at 9575,-540 h50 r270
  text "REV:" at 9665,-1335.1 h30 r270
  text ".PCB_REV" at 9575,-1350 h50 r270
  text "PART NO." at 3600,-1390 h45
  text ".PCB_PART_NUMBER" at 3915,-1390 h45
  text "UNLESS OTHERWISE SPECIFIED DIMENSIONS" at 3620,-1495 h45
  text "APPROVALS" at 5276,-1497.1 h45
  text "DATE" at 6136,-1497.1 h45
  text "2175 SALK AVENUE" at 8355,-1500 h45
  text "AND TOLERANCE ARE IN INCHES AND" at 3675,-1570 h45
  text "DESIGNER:" at 4956,-1577.1 h45
  text "SUITE 200" at 8355,-1590 h45
  text "APPLY TO THE FINISHED PART" at 3785,-1640 h45
  text ".PCB_DESIGNER" at 5276,-1657.1 h60
  text ".PCB_DESIGNER_APP_DATE" at 6006,-1657.1 h50
  text "CARLSBAD, CA 92008" at 8355,-1680.01 h45
  text "TOLERANCE ON:" at 4025,-1765 h45
  text "USA" at 8355,-1770 h45
  text "ENGINEER:" at 4956,-1777.1 h45
  text ".PCB_ENGINEER_APP_DATE" at 6006,-1847.1 h50
  text "2 DEC. PLACE" at 3620,-1855 h40
  text "3 DEC. PLACE" at 4075,-1855 h40
  text "ANGLES" at 4610,-1855 h40
  text ".PCB_ENGINEER" at 5276,-1857.1 h60
  text "TITLE:" at 6470,-1875 h45
  text "CHECKER:" at 4956,-1977.1 h45
  text ".PCB_2_DEC_TOL" at 3675,-2010 h60
  text ".PCB_3_DEC_TOL" at 4110,-2010 h60
  text ".PCB_ANG_TOL" at 4575,-2010 h60
  text ".PCB_TITLE_1" at 6645,-2025 h100
  text ".PCB_CHECKER_APP_DATE" at 6004,-2051.1 h50
  text ".PCB_CHECKER" at 5276,-2057.1 h60
  text "THIRD ANGLE PROJECTION" at 2847,-2070.1 h40
  text "A" at -5175,-2098 h70
  text "A" at 9625,-2098 h70
  text "MATERIAL:" at 3620,-2153.1 h45
  text "REFERENCE DOCUMENTS" at 5336,-2197.1 h45
  text "BOM:" at 4956,-2297.1 h45
  text ".PCB_TITLE_2" at 6640,-2320 h100
  text "SEE NOTES" at 3986,-2352.1 h60
  text ".DOC_NO_BOM" at 5276,-2387.1 h60
  text "ASSY DWG:" at 4956,-2487.1 h45
  text ".DOC_NO_ASSY_DWG" at 5276,-2577.1 h60
  text "SIZE:" at 6530,-2610 h45
  text "CAGE CODE:" at 6775,-2610 h45
  text "DWG NO:" at 7775,-2610 h45
  text "REV:" at 9335,-2610 h45
  text "FAB DWG:" at 4956,-2677.1 h45
  text ".PCB_DWG_NO" at 8085,-2750 h100
  text "B" at 6570,-2755 h100
  text ".PCB_REV" at 9365,-2755 h100
  text ".DOC_NO_FAB_DWG" at 5276,-2762.1 h60
  text ".CAGE_CODE" at 6945,-2765 h100
  text "SCHEMATIC:" at 4956,-2867.1 h45
  text "PRINT DATE:" at 3612,-2868.1 h45
  text "SCALE:" at 6470,-2925 h45
  text "FILE NAME:" at 7075,-2925.1 h45
  text "SHEET:" at 8815,-2925.1 h45
  text ".PRINT_DATE" at 4020,-2937.1 h60
  text ".Printout_Name" at -4994,-2947 h150
  text ".DOC_NO_SCH_DWG" at 5276,-2957.1 h60
  text ".PCB_FILE_NAME_NO_PATH" at 7418,-2970.1 h60
  text ".PCB_SCALE" at 6740,-2975 h60
  text "OF" at 9265,-2975.1 h45
  text "DOC-104 REV A" at -5050,-3042.1 h20
  text "6" at -4018.66,-3130 h70
  text "5" at -1523,-3130 h70
  text "4" at 966.34,-3130 h70
  text "3" at 3473.01,-3130 h70
  text "2" at 5972,-3130 h70
  text "1" at 8477,-3130 h70
22_TITLE_BLOCK_MIRRORED:
  drawing of 113 lines, arcs and shapes, not listed
  text "REV:" at -2665.1,6215 h30
  text "DWG. NO." at -1655.1,6215 h30
  text "1" at -3977,6170 h70
  text "2" at -1472,6170 h70
  text "3" at 1026.99,6170 h70
  text "4" at 3533.66,6170 h70
  text "5" at 6023,6170 h70
  text "6" at 8518.66,6170 h70
  text ".PCB_REV" at -2680,6125 h50
  text ".PCB_DWG_NO" at -1870,6125 h50
  text "R" at 7654.2,6027.61 h76
  text "O" at 7709.22,6027.61 h76
  text "N" at 7777.57,6027.61 h76
  text "I" at 7797.57,6027.61 h76
  text "E" at 7844.25,6027.61 h76
  text "R" at 7892.59,6027.61 h76
  text "E" at 7939.27,6027.61 h76
  text "H" at 7989.29,6027.61 h76
  text "D" at 8057.64,6027.61 h76
  text "E" at 8104.31,6027.61 h76
  text "S" at 8150.99,6027.61 h76
  text "O" at 8206.01,6027.61 h76
  text "L" at 8244.35,6027.61 h76
  text "C" at 8294.36,6027.61 h76
  text "S" at 8341.04,6027.61 h76
  text "I" at 8359.38,6027.61 h76
  text "D" at 8409.39,6027.61 h76
  text "A" at 8476.07,6027.61 h76
  text "T" at 8517.75,6027.61 h76
  text "A" at 8564.43,6027.61 h76
  text "D" at 8614.44,6027.61 h76
  text "E" at 8679.45,6027.61 h76
  text "H" at 8729.47,6027.61 h76
  text "T" at 8772.81,6027.61 h76
  text "D" at 8841.16,6027.61 h76
  text "N" at 8891.17,6027.61 h76
  text "A" at 8937.85,6027.61 h76
  text "T" at 9001.2,6027.61 h76
  text "N" at 9049.55,6027.61 h76
  text "E" at 9096.22,6027.61 h76
  text "M" at 9154.57,6027.61 h76
  text "U" at 9204.58,6027.61 h76
  text "C" at 9254.6,6027.61 h76
  text "O" at 9309.61,6027.61 h76
  text "D" at 9359.62,6027.61 h76
  text "S" at 9424.64,6027.61 h76
  text "I" at 9444.64,6027.61 h76
  text "H" at 9494.66,6027.61 h76
  text "T" at 9538,6027.61 h76
  text "REVISIONS" at -2890,5995 h60
  text "Y" at 7550.14,5947.59 h76
  text "A" at 7595.15,5947.59 h76
  text "M" at 7653.5,5947.59 h76
  text "D" at 7723.52,5947.59 h76
  text "N" at 7773.53,5947.59 h76
  text "A" at 7820.21,5947.59 h76
  text "D" at 7888.56,5947.59 h76
  text "E" at 7935.24,5947.59 h76
  text "T" at 7978.58,5947.59 h76
  text "I" at 7998.59,5947.59 h76
  text "M" at 8055.27,5947.59 h76
  text "I" at 8075.27,5947.59 h76
  text "L" at 8113.61,5947.59 h76
  text "M" at 8190.3,5947.59 h76
  text "U" at 8240.31,5947.59 h76
  text "I" at 8260.32,5947.59 h76
  text "T" at 8303.66,5947.59 h76
  text "L" at 8340.34,5947.59 h76
  text "A" at 8387.02,5947.59 h76
  text "F" at 8450.36,5947.59 h76
  text "O" at 8503.71,5947.59 h76
  text "Y" at 8568.73,5947.59 h76
  text "T" at 8612.07,5947.59 h76
  text "R" at 8660.42,5947.59 h76
  text "E" at 8707.09,5947.59 h76
  text "P" at 8753.77,5947.59 h76
  text "O" at 8807.82,5947.59 h76
  text "R" at 8857.83,5947.59 h76
  text "P" at 8904.51,5947.59 h76
  text "E" at 8969.53,5947.59 h76
  text "H" at 9019.54,5947.59 h76
  text "T" at 9062.88,5947.59 h76
  text "S" at 9127.9,5947.59 h76
  text "I" at 9147.9,5947.59 h76
  text "H" at 9216.25,5947.59 h76
  text "T" at 9259.6,5947.59 h76
  text "I" at 9277.94,5947.59 h76
  text "W" at 9346.29,5947.59 h76
  text "E" at 9391.3,5947.59 h76
  text "R" at 9441.31,5947.59 h76
  text "E" at 9487.99,5947.59 h76
  text "H" at 9538,5947.59 h76
  text "DATE" at -4055,5870 h60
  text "REV" at -1635,5870 h60
  text "ZONE" at -1305,5870 h60
  text "E" at 7769.92,5867.57 h76
  text "R" at 7819.93,5867.57 h76
  text "A" at 7866.61,5867.57 h76
  text "S" at 7931.63,5867.57 h76
  text "T" at 7974.97,5867.57 h76
  text "H" at 8023.32,5867.57 h76
  text "G" at 8078.33,5867.57 h76
  text "I" at 8098.34,5867.57 h76
  text "R" at 8146.68,5867.57 h76
  text "O" at 8221.7,5867.57 h76
  text "N" at 8271.71,5867.57 h76
  text "." at 8310.06,5867.57 h76
  text "E" at 8356.73,5867.57 h76
  text "L" at 8395.08,5867.57 h76
  text "O" at 8450.09,5867.57 h76
  text "H" at 8498.43,5867.57 h76
  text "W" at 8566.78,5867.57 h76
  text "N" at 8633.47,5867.57 h76
  text "I" at 8653.47,5867.57 h76
  text "D" at 8721.82,5867.57 h76
  text "E" at 8768.5,5867.57 h76
  text "T" at 8811.85,5867.57 h76
  text "U" at 8861.86,5867.57 h76
  text "B" at 8908.54,5867.57 h76
  text "I" at 8928.54,5867.57 h76
  text "R" at 8976.89,5867.57 h76
  text "T" at 9019.54,5867.57 h76
  text "S" at 9066.22,5867.57 h76
  text "I" at 9084.55,5867.57 h76
  text "D" at 9134.57,5867.57 h76
  text "Y" at 9201.25,5867.57 h76
  text "L" at 9239.59,5867.57 h76
  text "E" at 9286.27,5867.57 h76
  text "E" at 9331.28,5867.57 h76
  text "R" at 9381.29,5867.57 h76
  text "F" at 9424.64,5867.57 h76
  text "E" at 9491.32,5867.57 h76
  text "B" at 9538,5867.57 h76
  text "APPROVED" at -4560,5865 h60
  text "DESCRIPTION" at -2650,5865 h60
  text "." at 7617.96,5787.55 h76
  text "N" at 7666.3,5787.55 h76
  text "E" at 7712.98,5787.55 h76
  text "V" at 7759.66,5787.55 h76
  text "I" at 7779.66,5787.55 h76
  text "G" at 7834.68,5787.55 h76
  text "E" at 7895.93,5787.55 h76
  text "E" at 7942.61,5787.55 h76
  text "T" at 7985.95,5787.55 h76
  text "N" at 8034.3,5787.55 h76
  text "A" at 8080.97,5787.55 h76
  text "R" at 8130.99,5787.55 h76
  text "A" at 8177.66,5787.55 h76
  text "W" at 8246.01,5787.55 h76
  text "D" at 8312.7,5787.55 h76
  text "E" at 8359.38,5787.55 h76
  text "I" at 8379.38,5787.55 h76
  text "L" at 8416.06,5787.55 h76
  text "P" at 8462.74,5787.55 h76
  text "M" at 8521.08,5787.55 h76
  text "I" at 8541.09,5787.55 h76
  text "R" at 8609.44,5787.55 h76
  text "O" at 8664.45,5787.55 h76
  text "S" at 8729.47,5787.55 h76
  text "S" at 8776.15,5787.55 h76
  text "E" at 8822.82,5787.55 h76
  text "R" at 8872.84,5787.55 h76
  text "P" at 8919.51,5787.55 h76
  text "X" at 8964.53,5787.55 h76
  text "E" at 9011.2,5787.55 h76
  text "R" at 9081.22,5787.55 h76
  text "O" at 9136.23,5787.55 h76
  text "D" at 9204.58,5787.55 h76
  text "E" at 9251.26,5787.55 h76
  text "V" at 9297.94,5787.55 h76
  text "R" at 9347.95,5787.55 h76
  text "E" at 9394.63,5787.55 h76
  text "S" at 9441.31,5787.55 h76
  text "E" at 9487.99,5787.55 h76
  text "R" at 9538,5787.55 h76
  text "ORIGINAL" at -2725,5735 h60
  text "A" at -1665,5735 h60
  text "D" at -5125,5027 h70
  text "D" at 9675,5027 h70
  text "C" at -5125,2647 h70
  text "C" at 9675,2647 h70
  text "B" at -5125,272 h70
  text "B" at 9675,272 h70
  text "DWG. NO." at -5165,-325.1 h30 r90
  text ".PCB_DWG_NO" at -5075,-540 h50 r90
  text "REV:" at -5165,-1335.1 h30 r90
  text ".PCB_REV" at -5075,-1350 h50 r90
  text ".PCB_PART_NUMBER" at 585,-1390 h45
  text "PART NO." at 900,-1390 h45
  text "UNLESS OTHERWISE SPECIFIED DIMENSIONS" at 880,-1495 h45
  text "DATE" at -1636,-1497.1 h45
  text "APPROVALS" at -776,-1497.1 h45
  text "2175 SALK AVENUE" at -3855,-1500 h45
  text "AND TOLERANCE ARE IN INCHES AND" at 825,-1570 h45
  text "DESIGNER:" at -456,-1577.1 h45
  text "SUITE 200" at -3855,-1590 h45
  text "APPLY TO THE FINISHED PART" at 715,-1640 h45
  text ".PCB_DESIGNER_APP_DATE" at -1508,-1657.1 h50
  text ".PCB_DESIGNER" at -778,-1657.1 h60
  text "CARLSBAD, CA 92008" at -3855,-1680.01 h45
  text "TOLERANCE ON:" at 475,-1765 h45
  text "USA" at -3855,-1770 h45
  text "ENGINEER:" at -456,-1777.1 h45
  text ".PCB_ENGINEER_APP_DATE" at -1508,-1847.1 h50
  text "ANGLES" at -110,-1855 h40
  text "3 DEC. PLACE" at 425,-1855 h40
  text "2 DEC. PLACE" at 880,-1855 h40
  text ".PCB_ENGINEER" at -778,-1857.1 h60
  text "TITLE:" at -1970,-1875 h45
  text "CHECKER:" at -456,-1977.1 h45
  text ".PCB_ANG_TOL" at -75,-2010 h60
  text ".PCB_3_DEC_TOL" at 390,-2010 h60
  text ".PCB_2_DEC_TOL" at 825,-2010 h60
  text ".PCB_TITLE_1" at -2145,-2025 h100
  text ".PCB_CHECKER_APP_DATE" at -1506,-2051.1 h50
  text ".PCB_CHECKER" at -778,-2057.1 h60
  text "THIRD ANGLE PROJECTION" at 1653,-2070.1 h40
  text "A" at -5125,-2098 h70
  text "A" at 9675,-2098 h70
  text "MATERIAL:" at 880,-2153.1 h45
  text "REFERENCE DOCUMENTS" at -836,-2197.1 h45
  text "BOM:" at -456,-2297.1 h45
  text ".PCB_TITLE_2" at -2140,-2320 h100
  text "SEE NOTES" at 514,-2352.1 h60
  text ".DOC_NO_BOM" at -776,-2387.1 h60
  text "ASSY DWG:" at -456,-2487.1 h45
  text ".DOC_NO_ASSY_DWG" at -776,-2577.1 h60
  text "REV:" at -4835,-2610 h45
  text "DWG NO:" at -3275,-2610 h45
  text "CAGE CODE:" at -2275,-2610 h45
  text "SIZE:" at -2030,-2610 h45
  text "FAB DWG:" at -456,-2677.1 h45
  text ".PCB_DWG_NO" at -3585,-2750 h100
  text ".PCB_REV" at -4865,-2755 h100
  text "B" at -2070,-2755 h100
  text ".DOC_NO_FAB_DWG" at -776,-2762.1 h60
  text ".CAGE_CODE" at -2445,-2765 h100
  text "SCHEMATIC:" at -456,-2867.1 h45
  text "PRINT DATE:" at 888,-2868.1 h45
  text "SHEET:" at -4315,-2925.1 h45
  text "FILE NAME:" at -2575,-2925.1 h45
  text "SCALE:" at -1970,-2925 h45
  text ".PRINT_DATE" at 480,-2937.1 h60
  text ".Printout_Name" at 9494,-2947 h150
  text ".DOC_NO_SCH_DWG" at -776,-2957.1 h60
  text ".PCB_FILE_NAME_NO_PATH" at -2918,-2970.1 h60
  text "OF" at -4765,-2975.1 h45
  text ".PCB_SCALE" at -2240,-2975 h60
  text "DOC-104 REV A" at 9550,-3042.1 h20
  text "1" at -3977,-3130 h70
  text "2" at -1472,-3130 h70
  text "3" at 1026.99,-3130 h70
  text "4" at 3533.66,-3130 h70
  text "5" at 6023,-3130 h70
  text "6" at 8518.66,-3130 h70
